(* Logix 5000 project; controller HI5069_Sample_V30 vendor 1 type 14 code 196 rev 30.17; software revision 30.00 *)

TASK MainTask (continuous, watchdog 500 ms) : MainProgram, HARDY_HI5069_Scale_0, HARDY_HI5069_Scale_1

MODULES
   Local : vendor 1 type 14 code 196 (5069 0, rev 30.17)
      HARDY_HI5069_2WS : vendor 258 type 43 code 17 (5069 1, rev 1.1, StandardDataDriven RPI 4 ms)
END_MODULES

PROGRAM HARDY_HI5069_Scale_0   (* main routine MainRoutine *)
VAR
   C2_Cal_Scale : BOOL;
   C2_Scale_ONS1 : BOOL;
   C2_Scale_ONS2 : BOOL;
   C2_Search : BOOL;
   C2_Search_ONS1 : BOOL;
   C2UnlatchONS1 : BOOL;
   Command_Reset_TON1 : TIMER := (PRE := 2000);
   Display1 : BOOL;
   Gross_Weight_Display : REAL := 1.397919;
   Gross_Weight_Display_1DecPlace : REAL := 1.4;
   Gross_Wt_x10_DINT : DINT := 14;
   Last_Channel_Number_Sent : DINT := 1;
   Last_Command_Sent : DINT := 102;
   Last_Command_Status_Hex : DINT;
   Net_Weight_Display : REAL := 1.397919;
   Scan_Heartbeat_Display : SINT := -13;
   Set_Default_Params : BOOL;
   SetDefault_ONS1 : BOOL;
   Tare_Scale : BOOL;
   Tare_Scale_ONS1 : BOOL;
   TradCalHigh_ONS1 : BOOL;
   TradCalLow_ONS1 : BOOL;
   Traditional_Cal_High : BOOL;
   Traditional_Cal_Low : BOOL;
   Zero_Scale : BOOL;
   Zero_Scale_ONS1 : BOOL;
   zzzz : DINT;
END_VAR

ROUTINE MainRoutine   (* ladder *)
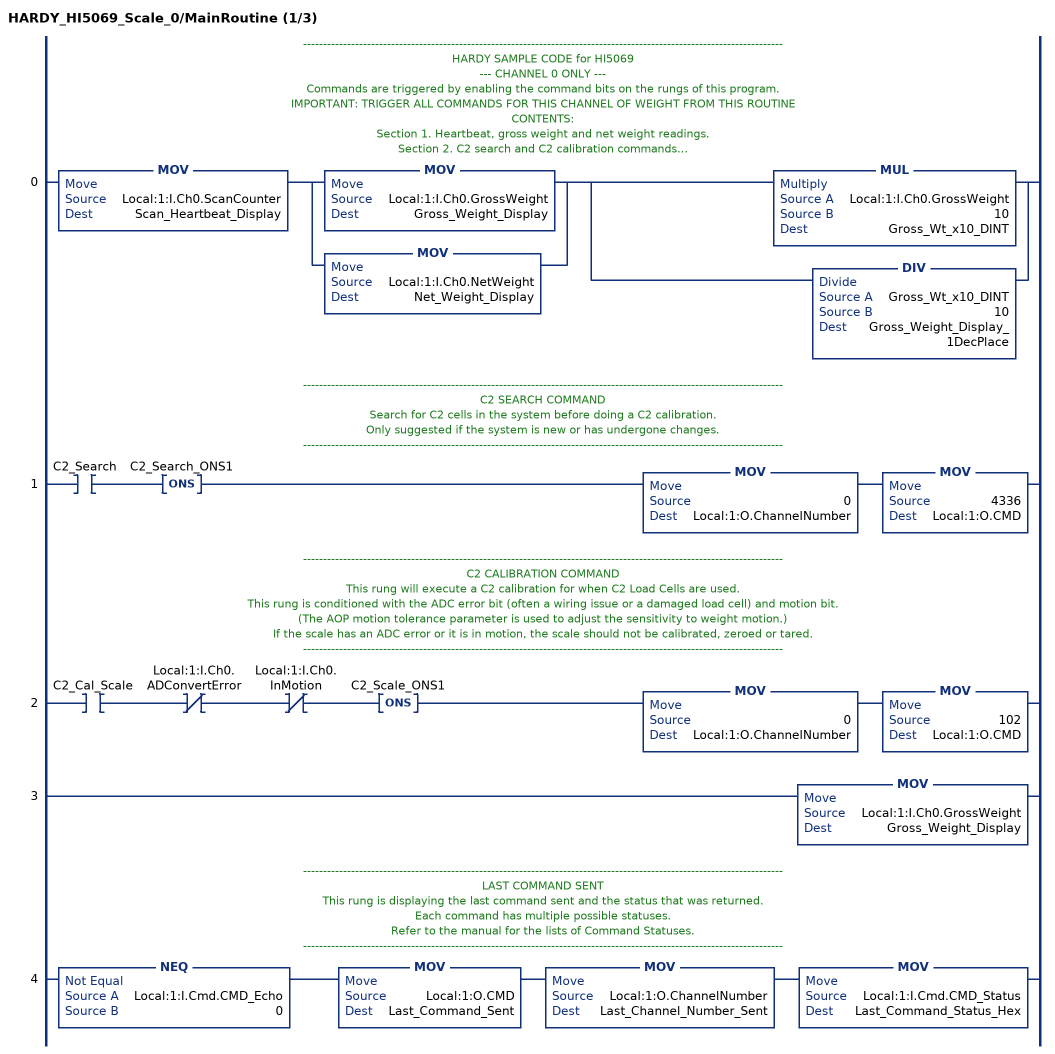
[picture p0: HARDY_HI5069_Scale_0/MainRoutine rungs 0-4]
   // ------------------------------------------------------------------------------------------------------------------------
   // HARDY SAMPLE CODE for HI5069
   // --- CHANNEL 0 ONLY ---
   // Commands are triggered by enabling the command bits on the rungs of this program.
   // IMPORTANT: TRIGGER ALL COMMANDS FOR THIS CHANNEL OF WEIGHT FROM THIS ROUTINE
   // CONTENTS:
   // Section 1. Heartbeat, gross weight and net weight readings.
   // Section 2. C2 search and C2 calibration commands.
   // Section 3. Last command sent and statuses
   // Section 4. Zero, Tare and other commands.
   // It is recommended to configure the parameters via the AOP prior to sending commands.
   // This is a display rung for the channel heartbeat, weight readings and an example of reducing the displayed number of decimal points.
   // ------------------------------------------------------------------------------------------------------------------------
   0: MOV(Local:1:I.Ch0.ScanCounter,Scan_Heartbeat_Display)[MOV(Local:1:I.Ch0.GrossWeight,Gross_Weight_Display) ,MOV(Local:1:I.Ch0.NetWeight,Net_Weight_Display) ][MUL(Local:1:I.Ch0.GrossWeight,10,Gross_Wt_x10_DINT) ,DIV(Gross_Wt_x10_DINT,10,Gross_Weight_Display_1DecPlace) ];
   // ------------------------------------------------------------------------------------------------------------------------
   // C2 SEARCH COMMAND
   // Search for C2 cells in the system before doing a C2 calibration.
   // Only suggested if the system is new or has undergone changes.
   // ------------------------------------------------------------------------------------------------------------------------
   1: XIC(C2_Search)ONS(C2_Search_ONS1)MOV(0,Local:1:O.ChannelNumber)MOV(4336,Local:1:O.CMD);
   // ------------------------------------------------------------------------------------------------------------------------
   // C2 CALIBRATION COMMAND
   // This rung will execute a C2 calibration for when C2 Load Cells are used.
   // This rung is conditioned with the ADC error bit (often a wiring issue or a damaged load cell) and motion bit.
   // (The AOP motion tolerance parameter is used to adjust the sensitivity to weight motion.)
   // If the scale has an ADC error or it is in motion, the scale should not be calibrated, zeroed or tared.
   // ------------------------------------------------------------------------------------------------------------------------
   2: XIC(C2_Cal_Scale)XIO(Local:1:I.Ch0.ADConvertError)XIO(Local:1:I.Ch0.InMotion)ONS(C2_Scale_ONS1)MOV(0,Local:1:O.ChannelNumber)MOV(102,Local:1:O.CMD);
   3: MOV(Local:1:I.Ch0.GrossWeight,Gross_Weight_Display);
   // ------------------------------------------------------------------------------------------------------------------------
   // LAST COMMAND SENT
   // This rung is displaying the last command sent and the status that was returned.
   // Each command has multiple possible statuses.
   // Refer to the manual for the lists of Command Statuses.
   // ------------------------------------------------------------------------------------------------------------------------
   4: NEQ(Local:1:I.Cmd.CMD_Echo,0)MOV(Local:1:O.CMD,Last_Command_Sent)MOV(Local:1:O.ChannelNumber,Last_Channel_Number_Sent)MOV(Local:1:I.Cmd.CMD_Status,Last_Command_Status_Hex);
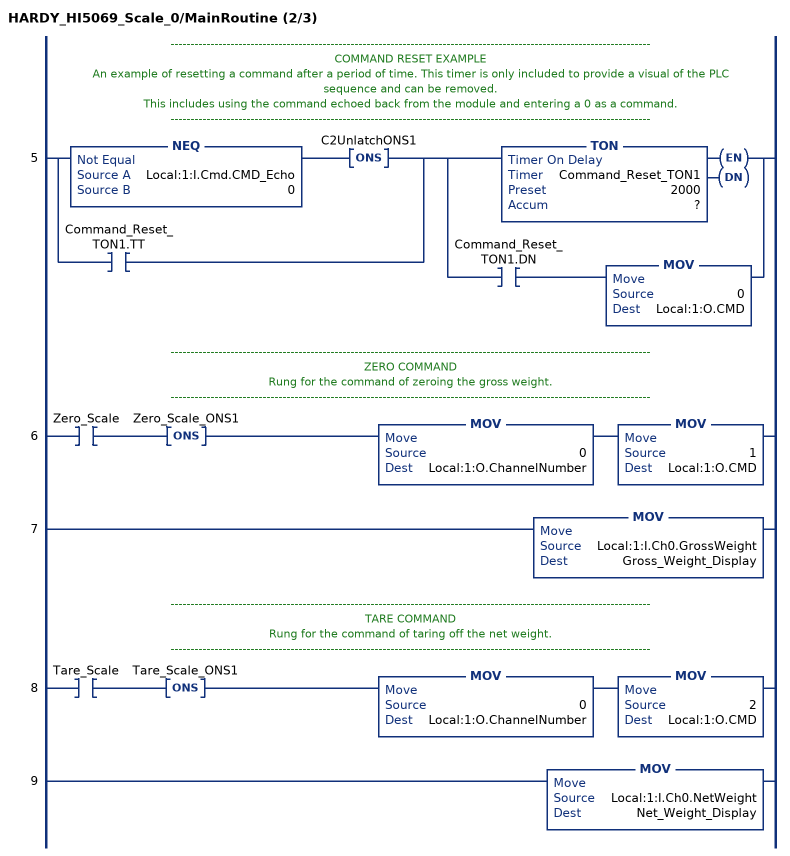
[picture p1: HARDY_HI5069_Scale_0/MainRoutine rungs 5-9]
   // ------------------------------------------------------------------------------------------------------------------------
   // COMMAND RESET EXAMPLE
   // An example of resetting a command after a period of time. This timer is only included to provide a visual of the PLC sequence and can be removed.
   // This includes using the command echoed back from the module and entering a 0 as a command.
   // ------------------------------------------------------------------------------------------------------------------------
   5: [NEQ(Local:1:I.Cmd.CMD_Echo,0) ONS(C2UnlatchONS1) ,XIC(Command_Reset_TON1.TT) ][TON(Command_Reset_TON1,?,?) ,XIC(Command_Reset_TON1.DN) MOV(0,Local:1:O.CMD) ];
   // ------------------------------------------------------------------------------------------------------------------------
   // ZERO COMMAND
   // Rung for the command of zeroing the gross weight.
   // ------------------------------------------------------------------------------------------------------------------------
   6: XIC(Zero_Scale)ONS(Zero_Scale_ONS1)MOV(0,Local:1:O.ChannelNumber)MOV(1,Local:1:O.CMD);
   7: MOV(Local:1:I.Ch0.GrossWeight,Gross_Weight_Display);
   // ------------------------------------------------------------------------------------------------------------------------
   // TARE COMMAND
   // Rung for the command of taring off the net weight.
   // ------------------------------------------------------------------------------------------------------------------------
   8: XIC(Tare_Scale)ONS(Tare_Scale_ONS1)MOV(0,Local:1:O.ChannelNumber)MOV(2,Local:1:O.CMD);
   9: MOV(Local:1:I.Ch0.NetWeight,Net_Weight_Display);
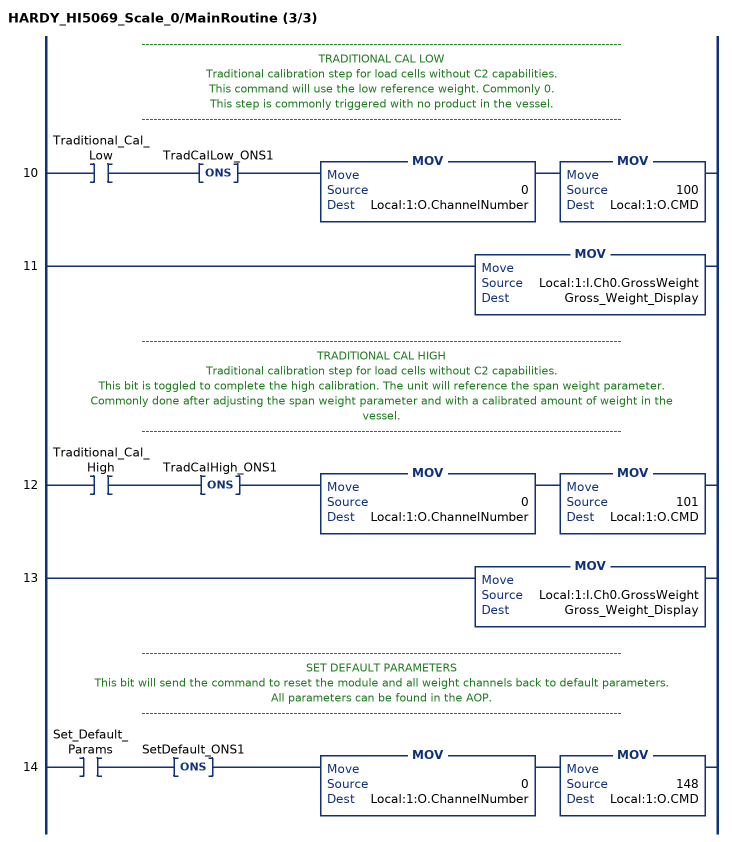
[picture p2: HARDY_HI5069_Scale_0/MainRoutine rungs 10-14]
   // ------------------------------------------------------------------------------------------------------------------------
   // TRADITIONAL CAL LOW
   // Traditional calibration step for load cells without C2 capabilities.
   // This command will use the low reference weight. Commonly 0.
   // This step is commonly triggered with no product in the vessel.
   // ------------------------------------------------------------------------------------------------------------------------
   10: XIC(Traditional_Cal_Low)ONS(TradCalLow_ONS1)MOV(0,Local:1:O.ChannelNumber)MOV(100,Local:1:O.CMD);
   11: MOV(Local:1:I.Ch0.GrossWeight,Gross_Weight_Display);
   // ------------------------------------------------------------------------------------------------------------------------
   // TRADITIONAL CAL HIGH
   // Traditional calibration step for load cells without C2 capabilities.
   // This bit is toggled to complete the high calibration. The unit will reference the span weight parameter.
   // Commonly done after adjusting the span weight parameter and with a calibrated amount of weight in the vessel.
   // ------------------------------------------------------------------------------------------------------------------------
   12: XIC(Traditional_Cal_High)ONS(TradCalHigh_ONS1)MOV(0,Local:1:O.ChannelNumber)MOV(101,Local:1:O.CMD);
   13: MOV(Local:1:I.Ch0.GrossWeight,Gross_Weight_Display);
   // ------------------------------------------------------------------------------------------------------------------------
   // SET DEFAULT PARAMETERS
   // This bit will send the command to reset the module and all weight channels back to default parameters.
   // All parameters can be found in the AOP.
   // ------------------------------------------------------------------------------------------------------------------------
   14: XIC(Set_Default_Params)ONS(SetDefault_ONS1)MOV(0,Local:1:O.ChannelNumber)MOV(148,Local:1:O.CMD);
END_ROUTINE
END_PROGRAM

PROGRAM HARDY_HI5069_Scale_1   (* main routine MainRoutine *)
VAR
   C2_Cal_Scale : BOOL;
   C2_Scale_ONS1 : BOOL;
   C2_Scale_ONS2 : BOOL;
   C2_Search : BOOL;
   C2_Search_ONS1 : BOOL;
   C2UnlatchONS1 : BOOL;
   Command_Reset_TON1 : TIMER := (PRE := 2000);
   Display1 : BOOL;
   Gross_Weight_Display : REAL := 0.0059821364;
   Gross_Weight_Display_1DecPlace : REAL;
   Gross_Wt_x10_DINT : DINT;
   Last_Channel_Number_Sent : DINT := 1;
   Last_Command_Sent : DINT := 102;
   Last_Command_Status_Hex : DINT;
   Net_Weight_Display : REAL := 0.0059821364;
   Scan_Heartbeat_Display : SINT := -8;
   Set_Default_Params : BOOL;
   SetDefault_ONS1 : BOOL;
   Tare_Scale : BOOL;
   Tare_Scale_ONS1 : BOOL;
   TradCalHigh_ONS1 : BOOL;
   TradCalLow_ONS1 : BOOL;
   Traditional_Cal_High : BOOL;
   Traditional_Cal_Low : BOOL;
   Zero_Scale : BOOL;
   Zero_Scale_ONS1 : BOOL;
   zzzz : DINT;
END_VAR

ROUTINE MainRoutine   (* ladder *)
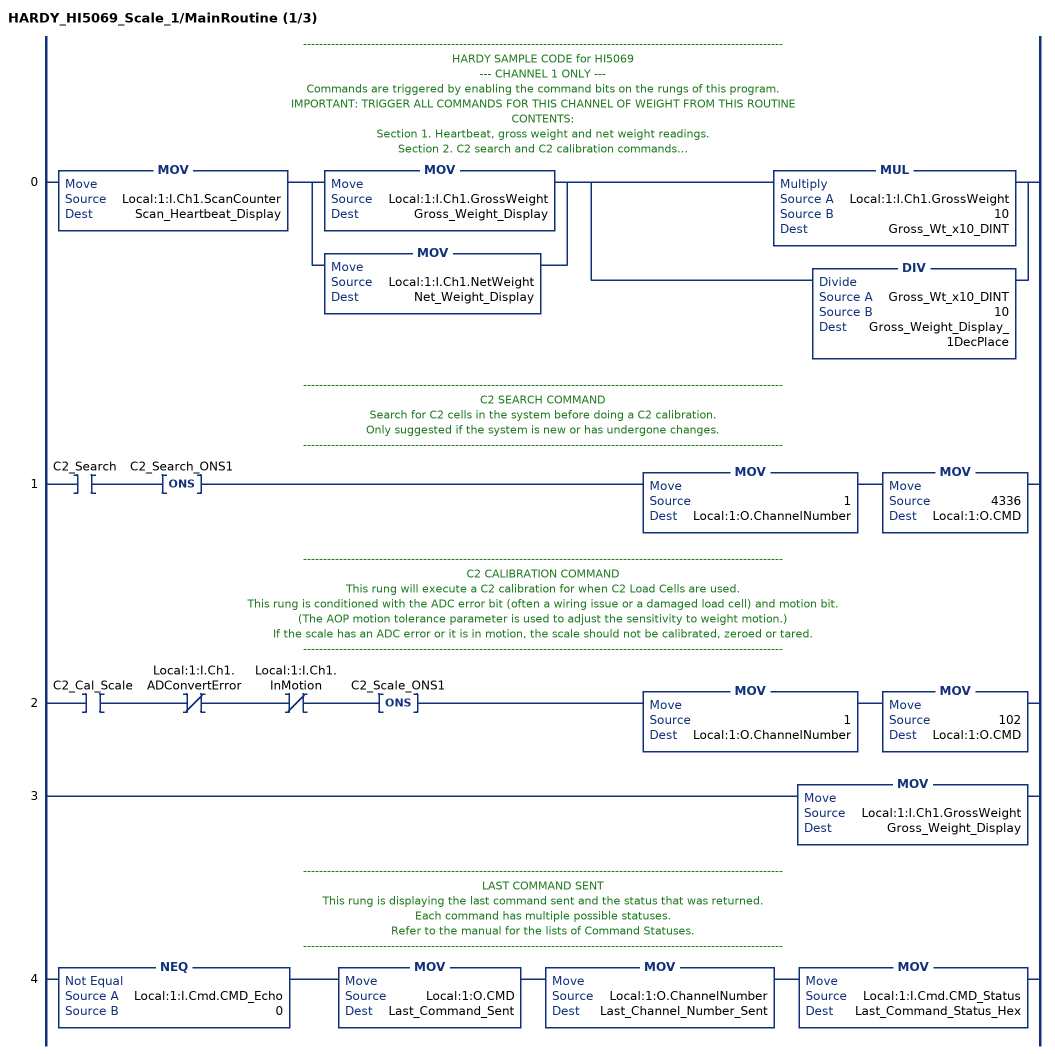
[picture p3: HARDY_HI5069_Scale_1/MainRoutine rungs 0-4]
   // ------------------------------------------------------------------------------------------------------------------------
   // HARDY SAMPLE CODE for HI5069
   // --- CHANNEL 1 ONLY ---
   // Commands are triggered by enabling the command bits on the rungs of this program.
   // IMPORTANT: TRIGGER ALL COMMANDS FOR THIS CHANNEL OF WEIGHT FROM THIS ROUTINE
   // CONTENTS:
   // Section 1. Heartbeat, gross weight and net weight readings.
   // Section 2. C2 search and C2 calibration commands.
   // Section 3. Last command sent and statuses
   // Section 4. Zero, Tare and other commands.
   // It is recommended to configure the parameters via the AOP prior to sending commands.
   // This is a display rung for the channel heartbeat, weight readings and an example of reducing the displayed number of decimal points.
   // ------------------------------------------------------------------------------------------------------------------------
   0: MOV(Local:1:I.Ch1.ScanCounter,Scan_Heartbeat_Display)[MOV(Local:1:I.Ch1.GrossWeight,Gross_Weight_Display) ,MOV(Local:1:I.Ch1.NetWeight,Net_Weight_Display) ][MUL(Local:1:I.Ch1.GrossWeight,10,Gross_Wt_x10_DINT) ,DIV(Gross_Wt_x10_DINT,10,Gross_Weight_Display_1DecPlace) ];
   // ------------------------------------------------------------------------------------------------------------------------
   // C2 SEARCH COMMAND
   // Search for C2 cells in the system before doing a C2 calibration.
   // Only suggested if the system is new or has undergone changes.
   // ------------------------------------------------------------------------------------------------------------------------
   1: XIC(C2_Search)ONS(C2_Search_ONS1)MOV(1,Local:1:O.ChannelNumber)MOV(4336,Local:1:O.CMD);
   // ------------------------------------------------------------------------------------------------------------------------
   // C2 CALIBRATION COMMAND
   // This rung will execute a C2 calibration for when C2 Load Cells are used.
   // This rung is conditioned with the ADC error bit (often a wiring issue or a damaged load cell) and motion bit.
   // (The AOP motion tolerance parameter is used to adjust the sensitivity to weight motion.)
   // If the scale has an ADC error or it is in motion, the scale should not be calibrated, zeroed or tared.
   // ------------------------------------------------------------------------------------------------------------------------
   2: XIC(C2_Cal_Scale)XIO(Local:1:I.Ch1.ADConvertError)XIO(Local:1:I.Ch1.InMotion)ONS(C2_Scale_ONS1)MOV(1,Local:1:O.ChannelNumber)MOV(102,Local:1:O.CMD);
   3: MOV(Local:1:I.Ch1.GrossWeight,Gross_Weight_Display);
   // ------------------------------------------------------------------------------------------------------------------------
   // LAST COMMAND SENT
   // This rung is displaying the last command sent and the status that was returned.
   // Each command has multiple possible statuses.
   // Refer to the manual for the lists of Command Statuses.
   // ------------------------------------------------------------------------------------------------------------------------
   4: NEQ(Local:1:I.Cmd.CMD_Echo,0)MOV(Local:1:O.CMD,Last_Command_Sent)MOV(Local:1:O.ChannelNumber,Last_Channel_Number_Sent)MOV(Local:1:I.Cmd.CMD_Status,Last_Command_Status_Hex);
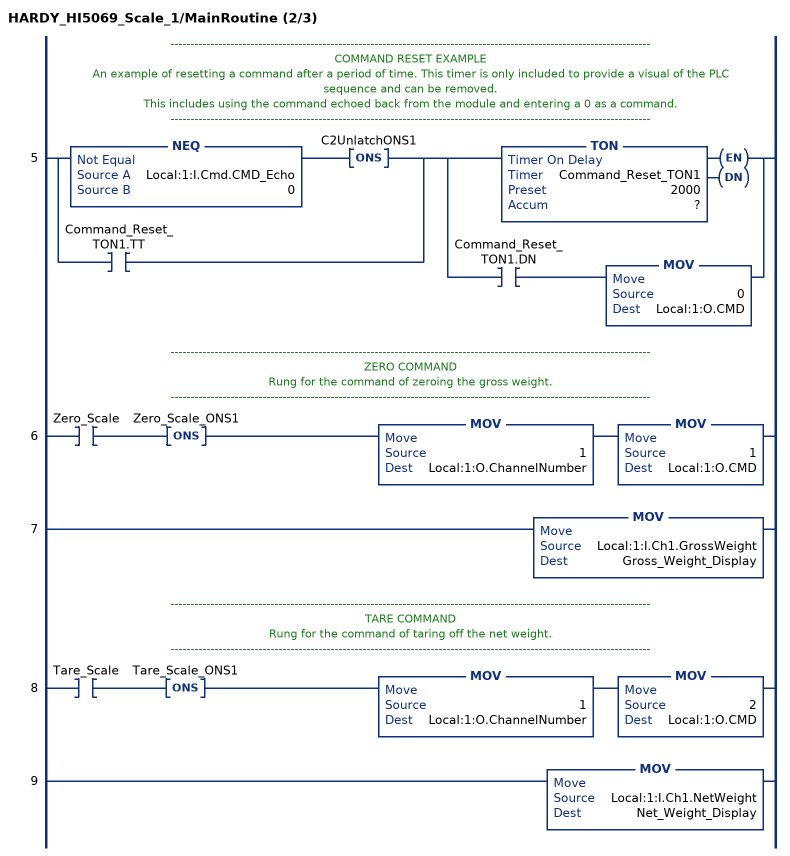
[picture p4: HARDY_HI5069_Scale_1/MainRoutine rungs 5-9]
   // ------------------------------------------------------------------------------------------------------------------------
   // COMMAND RESET EXAMPLE
   // An example of resetting a command after a period of time. This timer is only included to provide a visual of the PLC sequence and can be removed.
   // This includes using the command echoed back from the module and entering a 0 as a command.
   // ------------------------------------------------------------------------------------------------------------------------
   5: [NEQ(Local:1:I.Cmd.CMD_Echo,0) ONS(C2UnlatchONS1) ,XIC(Command_Reset_TON1.TT) ][TON(Command_Reset_TON1,?,?) ,XIC(Command_Reset_TON1.DN) MOV(0,Local:1:O.CMD) ];
   // ------------------------------------------------------------------------------------------------------------------------
   // ZERO COMMAND
   // Rung for the command of zeroing the gross weight.
   // ------------------------------------------------------------------------------------------------------------------------
   6: XIC(Zero_Scale)ONS(Zero_Scale_ONS1)MOV(1,Local:1:O.ChannelNumber)MOV(1,Local:1:O.CMD);
   7: MOV(Local:1:I.Ch1.GrossWeight,Gross_Weight_Display);
   // ------------------------------------------------------------------------------------------------------------------------
   // TARE COMMAND
   // Rung for the command of taring off the net weight.
   // ------------------------------------------------------------------------------------------------------------------------
   8: XIC(Tare_Scale)ONS(Tare_Scale_ONS1)MOV(1,Local:1:O.ChannelNumber)MOV(2,Local:1:O.CMD);
   9: MOV(Local:1:I.Ch1.NetWeight,Net_Weight_Display);
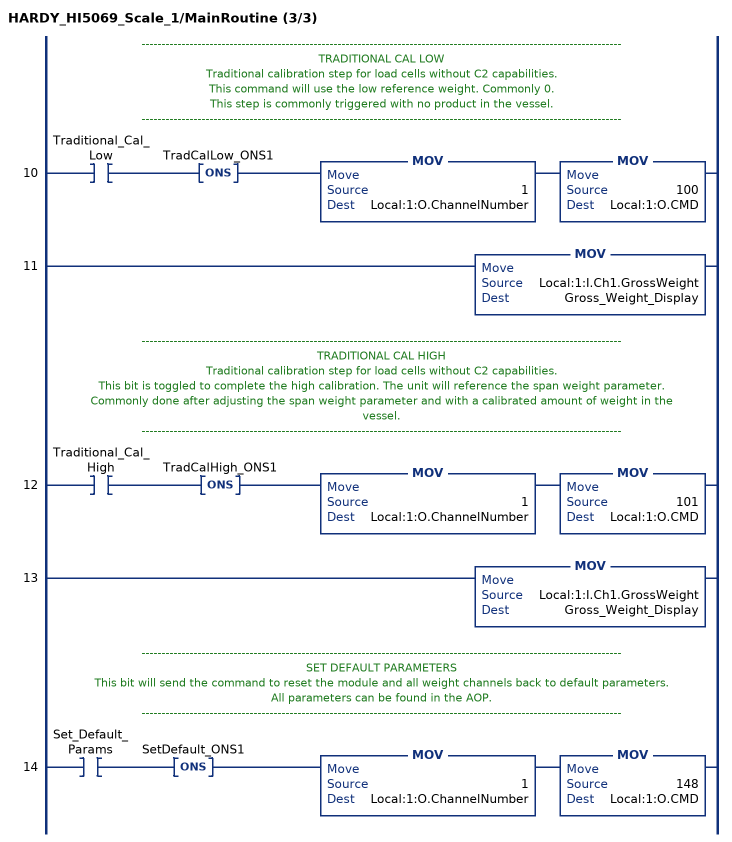
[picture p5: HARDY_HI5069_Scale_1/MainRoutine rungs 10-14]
   // ------------------------------------------------------------------------------------------------------------------------
   // TRADITIONAL CAL LOW
   // Traditional calibration step for load cells without C2 capabilities.
   // This command will use the low reference weight. Commonly 0.
   // This step is commonly triggered with no product in the vessel.
   // ------------------------------------------------------------------------------------------------------------------------
   10: XIC(Traditional_Cal_Low)ONS(TradCalLow_ONS1)MOV(1,Local:1:O.ChannelNumber)MOV(100,Local:1:O.CMD);
   11: MOV(Local:1:I.Ch1.GrossWeight,Gross_Weight_Display);
   // ------------------------------------------------------------------------------------------------------------------------
   // TRADITIONAL CAL HIGH
   // Traditional calibration step for load cells without C2 capabilities.
   // This bit is toggled to complete the high calibration. The unit will reference the span weight parameter.
   // Commonly done after adjusting the span weight parameter and with a calibrated amount of weight in the vessel.
   // ------------------------------------------------------------------------------------------------------------------------
   12: XIC(Traditional_Cal_High)ONS(TradCalHigh_ONS1)MOV(1,Local:1:O.ChannelNumber)MOV(101,Local:1:O.CMD);
   13: MOV(Local:1:I.Ch1.GrossWeight,Gross_Weight_Display);
   // ------------------------------------------------------------------------------------------------------------------------
   // SET DEFAULT PARAMETERS
   // This bit will send the command to reset the module and all weight channels back to default parameters.
   // All parameters can be found in the AOP.
   // ------------------------------------------------------------------------------------------------------------------------
   14: XIC(Set_Default_Params)ONS(SetDefault_ONS1)MOV(1,Local:1:O.ChannelNumber)MOV(148,Local:1:O.CMD);
END_ROUTINE
END_PROGRAM

PROGRAM MainProgram   (* main routine MainRoutine *)

ROUTINE MainRoutine   (* ladder *)
END_ROUTINE
END_PROGRAM
